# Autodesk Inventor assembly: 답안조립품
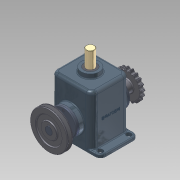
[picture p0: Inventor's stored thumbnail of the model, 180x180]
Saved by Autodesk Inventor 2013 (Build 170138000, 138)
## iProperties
Created: 2015-01
Part Number: 답안조립품
Document SubType Name: Assembly
Designer: hanacad7
Mass: 8618.01 g
Surface Area: 4424.06 cm^2
Volume: 1987.46 cm^3
Density: 4.33619 g/cm^3
Author: hanacad7
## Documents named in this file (15)
- C:\Documents and Settings\hanacad7\바탕 화면\350106V1007\답안조립품.iam
- C:\Documents and Settings\hanacad7\바탕 화면\350106V1007\본체.ipt
- C:\Documents and Settings\hanacad7\바탕 화면\350106V1007\M4x0.5.ipt
- C:\Documents and Settings\hanacad7\바탕 화면\350106V1007\베어링 6205.ipt
- C:\Documents and Settings\hanacad7\바탕 화면\350106V1007\체인 스프로킷.ipt
- C:\Documents and Settings\hanacad7\바탕 화면\350106V1007\커버.ipt
- C:\Documents and Settings\hanacad7\바탕 화면\350106V1007\멈춤나사 M5x0.5.ipt
- C:\Documents and Settings\hanacad7\바탕 화면\350106V1007\멈춤링.ipt
- C:\Documents and Settings\hanacad7\바탕 화면\350106V1007\오일실.ipt
- C:\Documents and Settings\hanacad7\바탕 화면\350106V1007\키 8x8.ipt
- C:\Documents and Settings\hanacad7\바탕 화면\350106V1007\편심축.ipt
- C:\Documents and Settings\hanacad7\바탕 화면\350106V1007\V-벨트풀리.ipt
- C:\Documents and Settings\hanacad7\바탕 화면\350106V1007\부시.ipt
- C:\Documents and Settings\hanacad7\바탕 화면\350106V1007\슬라이드.ipt
- C:\Documents and Settings\hanacad7\바탕 화면\350106V1007\가변 스프링.ipt
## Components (9 placed, 4 different names)
1. 5-체인 스프로킷:1 — 각도:3
2. V-벨트풀리:1 — 각도:2
3. 가변 스프링:1
4. M4x0.5:1
5. M4x0.5:2
6. M4x0.5:3
7. M4x0.5:4
8. M4x0.5:5
9. M4x0.5:6
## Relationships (2: Angle 2)
- 각도:2 [Angle]: V-벨트풀리:1
- 각도:3 [Angle]: 5-체인 스프로킷:1
